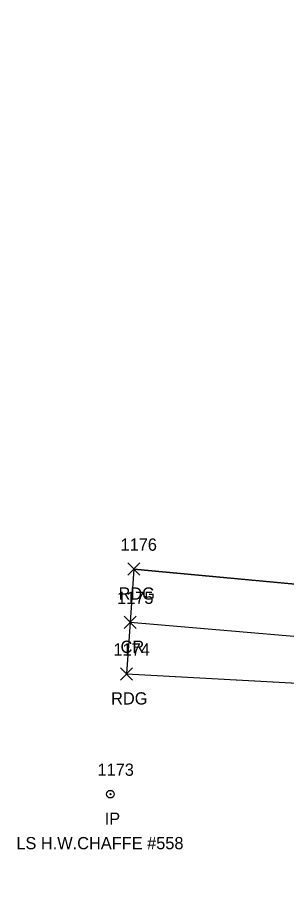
# Model space of a CAD drawing. Extents: x 1600281 to 1602254, y 862855 to 863227.
# Drawn here: x 1601703.6 to 1601747.6, y 862904.8 to 863049.7 of the extents above; entities that cross this region are included whole.
import ezdxf

# ---------------------------------------------------------------- set-up
doc = ezdxf.new("R2010")
doc.units = 0
for name, color, linetype in [('LSOGP', 7, 'Continuous'), ('M_A', 7, 'Continuous'), ('M_C', 7, 'Continuous'), ('M_I', 7, 'Continuous'), ('MPIR', 7, 'Continuous'), ('P_A', 7, 'Continuous'), ('P_I', 7, 'Continuous'), ('P_TIC', 7, 'Continuous'), ('PEU', 7, 'Continuous'), ('PRC', 7, 'Continuous')]:
    doc.layers.add(name, color=color, linetype=linetype)

msp = doc.modelspace()

# ---------------------------------------------------------------- linework, layer by layer
at = {"layer": 'LSOGP'}
msp.add_lwpolyline([(1601752.51, 862956.82), (1601742.56, 862957.76), (1601732.6, 862958.69), (1601722.64, 862959.62), (1601722.03, 862950.92), (1601721.43, 862942.48), (1601731.42, 862941.94), (1601741.4, 862941.39), (1601751.39, 862940.85)], dxfattribs=at)
at = {"layer": 'MPIR'}
for radius in [0.625, 0.0833]:
    msp.add_circle((1601718.81, 862922.83), radius, dxfattribs=at)
at = {"layer": 'P_TIC'}
for points in [[(1601721.64, 862958.62), (1601723.64, 862960.62)], [(1601723.64, 862958.62), (1601721.64, 862960.62)], [(1601721.03, 862949.92), (1601723.03, 862951.92)], [(1601723.03, 862949.92), (1601721.03, 862951.92)], [(1601720.43, 862941.48), (1601722.43, 862943.48)], [(1601722.43, 862941.48), (1601720.43, 862943.48)]]:
    msp.add_lwpolyline(points, dxfattribs=at)
at = {"layer": 'PEU'}
for points in [[(1601721.43, 862942.48), (1601759.39, 862940.42), (1601795.48, 862935.05), (1601824.44, 862931.28), (1601871.6, 862925.25), (1601900.95, 862923.39), (1601930.54, 862915.16), (1601956.45, 862910.48), (1601973.53, 862907.72), (1601992.87, 862904.84), (1602011.43, 862910.06), (1602025.54, 862921.56), (1602034.6, 862951.41), (1602037.17, 862973.14), (1602036.63, 863000.37), (1602039.38, 863008.7), (1602041.94, 863026.81), (1602046.4, 863038.48), (1602048.21, 863041.76), (1602041.55, 863045.82), (1602034.19, 863049.73), (1602032.2, 863046.61)], [(1601722.64, 862959.62), (1601760.79, 862956.05), (1601799.29, 862951.59), (1601828.84, 862949.76), (1601875.05, 862946.51), (1601907.83, 862943.55), (1601935.49, 862931.23), (1601958.79, 862926.46), (1601973.44, 862925.27), (1601984.38, 862925.96), (1601999.67, 862930.14), (1602015.04, 862942.76), (1602018.56, 862960.18), (1602022.83, 862979.22), (1602021.22, 863002.76), (1602025.96, 863016.12), (1602028.23, 863030.49), (1602032.2, 863046.61)]]:
    msp.add_lwpolyline(points, dxfattribs=at)
at = {"layer": 'PRC'}
msp.add_lwpolyline([(1601722.03, 862950.92), (1601760.35, 862947.65), (1601797.64, 862942.06), (1601826.1, 862939.87), (1601874.38, 862936.2), (1601906.56, 862932.66), (1601933.52, 862923.27), (1601957.93, 862920.04), (1601974.08, 862916.23), (1601989.5, 862915.67), (1602005.13, 862920.56), (1602020.05, 862931.21), (1602025.88, 862956.8), (1602029.68, 862975.25), (1602029.18, 863001.63), (1602032.15, 863012.73), (1602036.07, 863028.12), (1602041.55, 863045.82)], dxfattribs=at)

# ---------------------------------------------------------------- texts
at = {"layer": 'M_A'}
msp.add_text('IP', height=2, dxfattribs=at).set_placement((1601717.86, 862917.83))
at = {"layer": 'M_C'}
msp.add_text('LS H.W.CHAFFE #558', height=2, dxfattribs=at).set_placement((1601703.41, 862913.83))
at = {"layer": 'M_I'}
msp.add_text('1173', height=2, dxfattribs=at).set_placement((1601716.69, 862925.83))
at = {"layer": 'P_A'}
for s, p in [('RDG', (1601720.13, 862954.62)), ('CR', (1601720.46, 862945.92)), ('RDG', (1601718.92, 862937.48))]:
    msp.add_text(s, height=2, dxfattribs=at).set_placement(p)
at = {"layer": 'P_I'}
for s, p in [('1176', (1601720.46, 862962.62)), ('1175', (1601719.9, 862953.92)), ('1174', (1601719.3, 862945.48))]:
    msp.add_text(s, height=2, dxfattribs=at).set_placement(p)

doc.saveas('drawing.dxf')
